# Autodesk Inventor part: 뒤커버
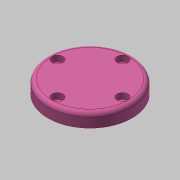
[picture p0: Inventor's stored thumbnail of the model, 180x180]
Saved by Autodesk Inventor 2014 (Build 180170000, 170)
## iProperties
Created: 2015-09
Part Number: 뒤커버
Material: 알루미늄 6061
Document SubType Name: Modeling
Designer: mduedu
Density: 1 g/cm^3
Appearance: 분홍색
Author: mduedu
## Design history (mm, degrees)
sketch "스케치1"
  geometry: L1 (0, 7.5)-(0, -7.5); L2 (0, 7.5)-(31, 7.5); L3 (31, 7.5)-(31, -2.5); L4 (31, -2.5)-(17.5, -2.5); L5 (17.5, -2.5)-(17.5, -7.5); L6 (17.5, -7.5)-(0, -7.5); 2 further points
  constraints: 12 end point, 2 parallel, 2 perpendicular, 1 coincident, 1 horizontal, 1 midpoint, 1 vertical
  dimensions: "d0" = 15 distance of L1.start L1.end; "d1" = 62 diameter of L3 L1; "d2" = 35 diameter of L5 L1; "d3" = 10 distance of L2.end L3.end
revolve "회전1" sketch "스케치1" stored, may be unused: angle "d4" = 90 deg
fillet "모깎기2" dims "d48" = 3
sketch "스케치4" dims "d49" = 48
  geometry: 3 further points
  constraints: 2 vertical alignment, 1 coincident, 2 other
hole "구멍4" sketch "스케치4" at (0, 24) diameter "d50" = 4.5; stored, may be unused: countersink angle "d54" = 90 deg, drill point angle "d56" = 118 deg; dims "d51" = 6, "d52" = 8, "d53" = 4.4, "d55" = 8
hole "구멍5" diameter "d62" = 24; stored, may be unused: countersink angle "d66" = 90 deg, drill point angle "d68" = 0 deg; dims "d60" = 10, "d61" = 10, "d63" = 6, "d64" = 4, "d65" = 2, "d67" = 8
fillet "모깎기3" dims "d69" = 3
chamfer "모따기3" distance "d43" = 1; stored, may be unused: second distance "d44" = 2, angle "d45" = 45 deg
node "솔리드1"
pattern_circular "원형 패턴1" dims angle "d58" = 360 deg
